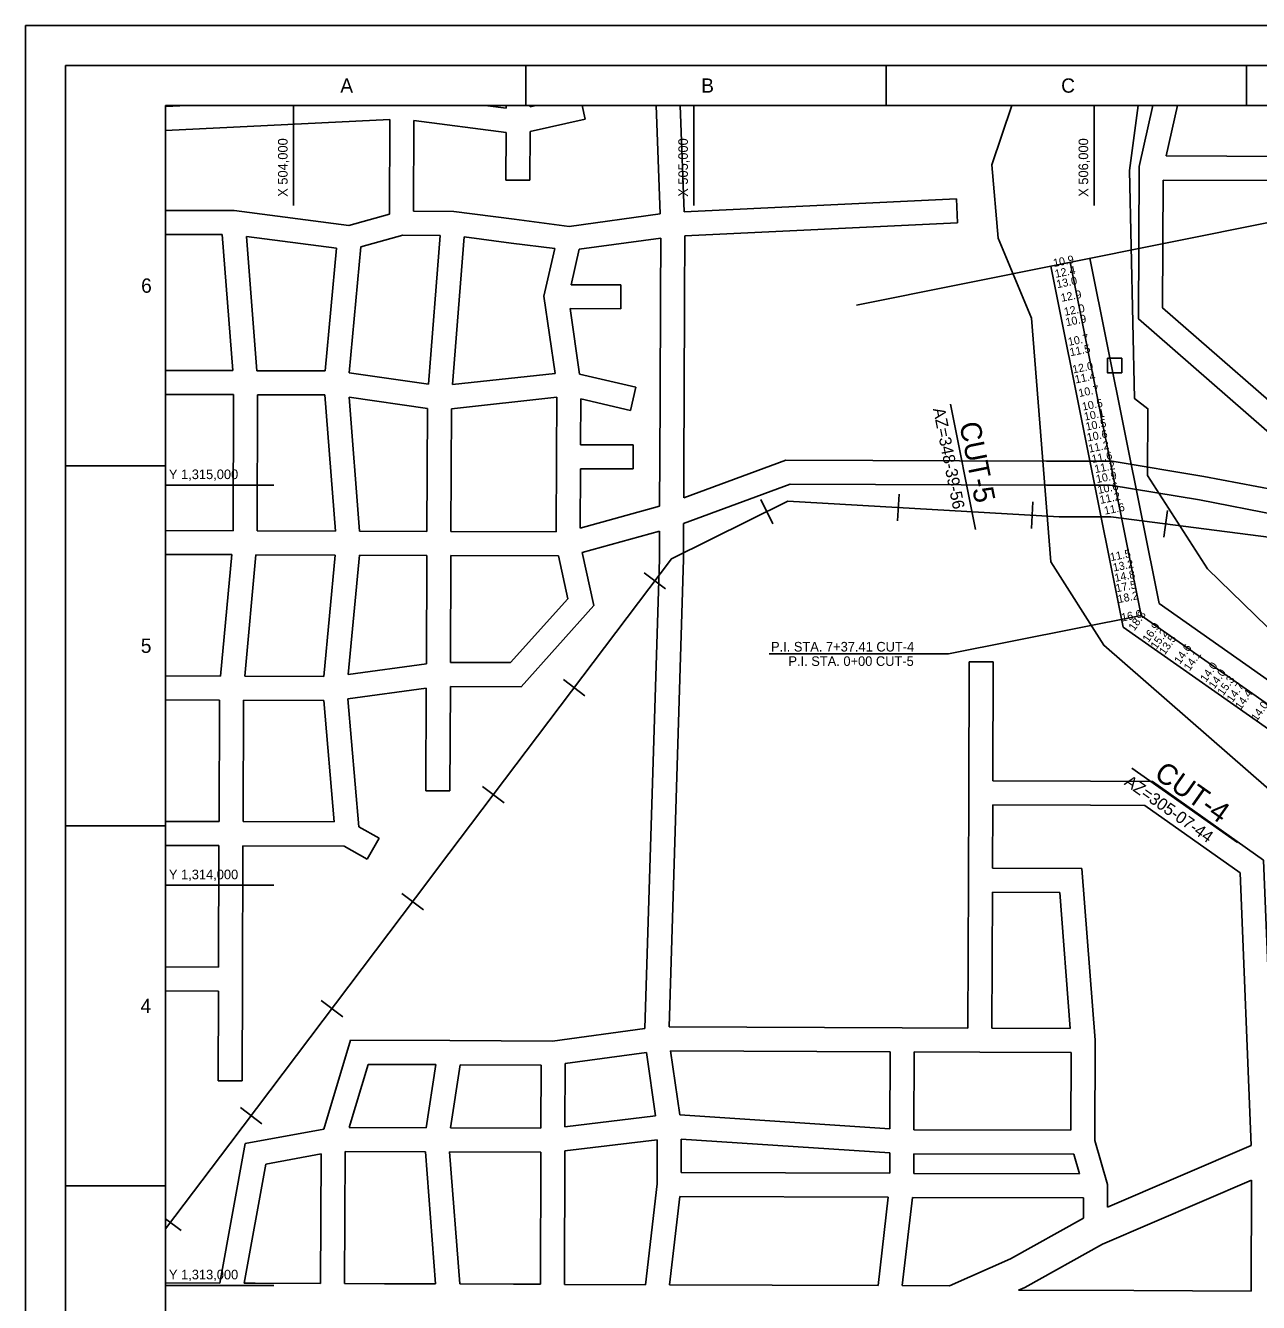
# Model space of a CAD drawing. Extents: x 503330 to 511530, y 1310349 to 1316149.
# Drawn here: x 503330 to 506410, y 1312957 to 1316149 of the extents above; entities that cross this region are included whole.
import ezdxf

# ---------------------------------------------------------------- set-up
doc = ezdxf.new("R2010")
doc.units = 0
for name, color, linetype in [('G-ANNO-TTLB', 7, 'Continuous'), ('Level 2', 7, 'Continuous'), ('Level 23', 7, 'Continuous'), ('Level 3', 7, 'Continuous'), ('Level 32', 7, 'Continuous'), ('Level 37', 7, 'Continuous'), ('Level 49', 7, 'Continuous'), ('Level 5', 7, 'Continuous'), ('Level 50', 7, 'Continuous'), ('Level 51', 7, 'Continuous'), ('Level 52', 7, 'Continuous'), ('Level 56', 7, 'Continuous'), ('Level 58', 7, 'Continuous'), ('Level 6', 7, 'Continuous')]:
    doc.layers.add(name, color=color, linetype=linetype)

msp = doc.modelspace()

# ---------------------------------------------------------------- linework, layer by layer
at = {"layer": 'G-ANNO-TTLB'}
for p, q in [((503430.3, 1316048.5), (503430.3, 1310448.5)), ((511430.3, 1316048.5), (503430.3, 1316048.5)), ((504580.3, 1315948.5), (504580.3, 1316048.5)), ((505480.3, 1315948.5), (505480.3, 1316048.5)), ((506380.3, 1315948.5), (506380.3, 1316048.5)), ((503680.3, 1310548.5), (503680.3, 1315948.5)), ((503680.3, 1315948.5), (511330.3, 1315948.5)), ((503680.3, 1315048.5), (503430.3, 1315048.5)), ((503680.3, 1314148.5), (503430.3, 1314148.5)), ((503680.3, 1313248.5), (503430.3, 1313248.5))]:
    msp.add_line(p, q, dxfattribs=at)
for points in [[(503330.3, 1310348.5), (511530.3, 1310348.5), (511530.3, 1316148.5), (503330.3, 1316148.5)], [(503330.3, 1310348.5), (511530.3, 1310348.5), (511530.3, 1316148.5), (503330.3, 1316148.5)], [(503330.3, 1316148.5), (511530.3, 1316148.5), (511530.3, 1310348.5), (503330.3, 1310348.5)]]:
    msp.add_lwpolyline(points, close=True, dxfattribs=at)
msp.add_lwpolyline([(503330.3, 1316098.5), (503330.3, 1316148.5), (503380.3, 1316148.5)], dxfattribs=at)
at = {"layer": 'Level 2'}
for p, q in [((504000, 1315698.5), (504000, 1315948.5)), ((505000, 1315698.5), (505000, 1315948.5)), ((506000, 1315698.5), (506000, 1315948.5)), ((503680.3, 1315000), (503950.3, 1315000)), ((503680.3, 1314000), (503950.3, 1314000)), ((503680.3, 1313000), (503950.3, 1313000))]:
    msp.add_line(p, q, dxfattribs=at)
at = {"layer": 'Level 23'}
for p, q in [((506392.1, 1313349.5), (506033.2, 1313195.7)), ((506393.2, 1313262.9), (506020.6, 1313103.3)), ((505973.1, 1313168.3), (505790.9, 1313066.7)), ((506020.6, 1313103.3), (505826.8, 1312995.1)), ((505790.9, 1313066.7), (505638.7, 1312998.8)), ((503815.9, 1313005.8), (503680.3, 1313006.3)), ((503903.8, 1313005.4), (503876.8, 1313005.5)), ((504067.5, 1313004.8), (503903.8, 1313005.4)), ((504226.7, 1313004.2), (504127.5, 1313004.6)), ((504354.8, 1313003.7), (504226.7, 1313004.2)), ((504549.5, 1313003), (504415, 1313003.5)), ((504616.4, 1313002.7), (504549.5, 1313003)), ((504878.9, 1313001.7), (504676.4, 1313002.5)), ((505195.3, 1313000.5), (504939.3, 1313001.5)), ((505460.1, 1312999.5), (505195.3, 1313000.5)), ((505638.7, 1312998.8), (505520.5, 1312999.3)), ((505826.8, 1312995.1), (505811.2, 1312988.1))]:
    msp.add_line(p, q, dxfattribs=at)
at = {"layer": 'Level 32'}
for p, q in [((503733.7, 1315948.5), (503680.3, 1315945.9)), ((504530.8, 1315941.8), (504478.9, 1315948.5)), ((504530.8, 1315941.8), (504530.8, 1315948.5)), ((504590.8, 1315945.1), (504590.8, 1315948.5)), ((504606.3, 1315948.5), (504590.8, 1315945.1)), ((504728.7, 1315914.2), (504721.1, 1315948.5)), ((504916.1, 1315677.8), (504905.7, 1315948.5)), ((504975.9, 1315683.2), (504965.7, 1315948.5)), ((506112.2, 1315796), (506146.7, 1315948.5)), ((506179.7, 1315822.5), (506208.2, 1315948.5)), ((504240.1, 1315913.7), (503680.3, 1315885.8)), ((504239.2, 1315677.2), (504240.1, 1315913.7)), ((504299.3, 1315684.2), (504300.1, 1315911.1)), ((504530.6, 1315881.4), (504300.1, 1315911.1)), ((504728.7, 1315914.2), (504590.6, 1315883.6)), ((504530.1, 1315762.4), (504530.6, 1315881.4)), ((504590.1, 1315762.2), (504590.6, 1315883.6)), ((506492, 1315821.3), (506179.7, 1315822.5)), ((504530.1, 1315762.4), (504590.1, 1315762.2)), ((506478.3, 1315761.4), (506172.1, 1315762.5)), ((505656.1, 1315715.4), (504975.9, 1315683.2)), ((505658.9, 1315655.4), (505656.1, 1315715.4)), ((503851.4, 1315686), (503680.3, 1315686.6)), ((504137.7, 1315649), (503851.4, 1315686)), ((504400.3, 1315683.8), (504299.3, 1315684.2)), ((504550.9, 1315664.5), (504400.3, 1315683.8)), ((504239.2, 1315677.2), (504137.7, 1315649)), ((504688.6, 1315646.7), (504550.9, 1315664.5)), ((504916.1, 1315677.8), (504688.6, 1315646.7)), ((505658.9, 1315655.4), (504977, 1315623.1)), ((503821.7, 1315626.1), (503680.3, 1315626.6)), ((503847.8, 1315286.1), (503821.7, 1315626.1)), ((503908, 1315285.8), (503882.2, 1315621.5)), ((504107.3, 1315592.4), (503882.2, 1315621.5)), ((504273.2, 1315624.3), (504167.8, 1315595.1)), ((504365.9, 1315624), (504273.2, 1315624.3)), ((504336.9, 1315252), (504365.9, 1315624)), ((504397, 1315251.5), (504425.7, 1315620.1)), ((504543.2, 1315605), (504425.7, 1315620.1)), ((504917, 1315617.4), (504713.4, 1315589.5)), ((504916.4, 1315470.1), (504917, 1315617.4)), ((504976.4, 1315469.9), (504977, 1315623.1)), ((504078.8, 1315285.2), (504107.3, 1315592.4)), ((504138.7, 1315280.7), (504167.8, 1315595.1)), ((504652.2, 1315590.9), (504543.2, 1315605)), ((504625.4, 1315472.3), (504652.2, 1315590.9)), ((504693.4, 1315500.9), (504713.4, 1315589.5)), ((504817.4, 1315500.5), (504693.4, 1315500.9)), ((504817.2, 1315440.5), (504817.4, 1315500.5)), ((504653.2, 1315279.3), (504625.4, 1315472.3)), ((504915.5, 1315215.6), (504916.4, 1315470.1)), ((504975.4, 1315215.4), (504976.4, 1315469.9)), ((504817.2, 1315440.5), (504690.5, 1315441)), ((504714.1, 1315277.5), (504690.5, 1315441)), ((503847.8, 1315286.1), (503680.3, 1315286.7)), ((504078.8, 1315285.2), (503908, 1315285.8)), ((504336.9, 1315252), (504138.7, 1315280.7)), ((504653.2, 1315279.3), (504397, 1315251.5)), ((504855.3, 1315245.1), (504714.1, 1315277.5)), ((504841.9, 1315186.6), (504855.3, 1315245.1)), ((503850.1, 1315226.1), (503680.3, 1315226.7)), ((503848.8, 1314886.1), (503850.1, 1315226.1)), ((503908.8, 1314885.9), (503910.1, 1315225.8)), ((504078.4, 1315225.2), (503910.1, 1315225.8)), ((504104.5, 1314885.2), (504078.4, 1315225.2)), ((504334.2, 1315191.8), (504139, 1315220)), ((504164.7, 1314884.9), (504139, 1315220)), ((504657.2, 1315219.4), (504394.2, 1315190.8)), ((504656.6, 1315071.2), (504657.2, 1315219.4)), ((504716.7, 1315100.9), (504717.2, 1315215.2)), ((504841.9, 1315186.6), (504717.2, 1315215.2)), ((504914.9, 1315070.2), (504915.5, 1315215.6)), ((504974.9, 1315070), (504975.4, 1315215.4)), ((504333, 1314884.3), (504334.2, 1315191.8)), ((504393, 1314884.1), (504394.2, 1315190.8)), ((504848.2, 1315100.4), (504716.7, 1315100.9)), ((504847.9, 1315040.4), (504848.2, 1315100.4)), ((504655.9, 1314883), (504656.6, 1315071.2)), ((504914.4, 1314947.5), (504914.9, 1315070.2)), ((504974.5, 1314967.8), (504974.9, 1315070)), ((506045, 1315059.5), (505881.1, 1315060.1)), ((506045, 1315059.5), (506273.6, 1315021.9)), ((504715.9, 1314892.4), (504716.5, 1315040.9)), ((504847.9, 1315040.4), (504716.5, 1315040.9)), ((506273.6, 1315021.9), (506450.8, 1314987.9)), ((506039.9, 1314999.5), (505880.9, 1315000.2)), ((506039.9, 1314999.5), (506263, 1314962.8)), ((504914.4, 1314947.5), (504715.9, 1314892.4)), ((506263, 1314962.8), (506459, 1314925.2)), ((503848.8, 1314886.1), (503680.3, 1314886.8)), ((504104.5, 1314885.2), (503908.8, 1314885.9)), ((504333, 1314884.3), (504164.7, 1314884.9)), ((504655.9, 1314883), (504393, 1314884.1)), ((504914.2, 1314885.2), (504721.1, 1314831.6)), ((504913.9, 1314816.1), (504914.2, 1314885.2)), ((504973.9, 1314815.1), (504974.3, 1314903.8)), ((503845.8, 1314826.2), (503680.3, 1314826.8)), ((503817.6, 1314522.7), (503845.8, 1314826.2)), ((503877.9, 1314522.5), (503906, 1314825.9)), ((504104, 1314825.2), (503906, 1314825.9)), ((504075.9, 1314521.7), (504104, 1314825.2)), ((504136.6, 1314526.5), (504164.3, 1314824.9)), ((504332.8, 1314824.3), (504164.3, 1314824.9)), ((504331.8, 1314553.2), (504332.8, 1314824.3)), ((504391.8, 1314556.9), (504392.8, 1314824.1)), ((504661.6, 1314823), (504392.8, 1314824.1)), ((504684.9, 1314716), (504661.6, 1314823)), ((504750.1, 1314698.8), (504721.1, 1314831.6)), ((504877.8, 1313642.3), (504913.9, 1314816.1)), ((504938, 1313645.9), (504973.9, 1314815.1)), ((504542, 1314556.3), (504684.9, 1314716)), ((504568.7, 1314496.2), (504750.1, 1314698.8)), ((504331.8, 1314553.2), (504136.6, 1314526.5)), ((504542, 1314556.3), (504391.8, 1314556.9)), ((505686.5, 1314231.1), (505687.8, 1314558.3)), ((505687.8, 1314558.3), (505747.8, 1314558)), ((505746.7, 1314260.8), (505747.8, 1314558)), ((503817.6, 1314522.7), (503680.3, 1314523.2)), ((504075.9, 1314521.7), (503877.9, 1314522.5)), ((504331.5, 1314492.6), (504135.5, 1314465.8)), ((504330.5, 1314236.2), (504331.5, 1314492.6)), ((504390.5, 1314236), (504391.6, 1314496.9)), ((504568.7, 1314496.2), (504391.6, 1314496.9)), ((503814.8, 1314462.7), (503680.3, 1314463.2)), ((503813.7, 1314159.2), (503814.8, 1314462.7)), ((503873.7, 1314158.9), (503874.8, 1314462.5)), ((504075.7, 1314461.7), (503874.8, 1314462.5)), ((504101.5, 1314158.1), (504075.7, 1314461.7)), ((504162.7, 1314146.2), (504135.5, 1314465.8)), ((505991.1, 1314259.9), (505746.7, 1314260.8)), ((504330.5, 1314236.2), (504390.5, 1314236)), ((505685.7, 1314012.9), (505686.5, 1314231.1)), ((505745.8, 1314042.7), (505746.4, 1314200.8)), ((505990.9, 1314199.9), (505746.4, 1314200.8)), ((503813.7, 1314159.2), (503680.3, 1314159.7)), ((504101.5, 1314158.1), (503873.7, 1314158.9)), ((504213.4, 1314117.4), (504162.7, 1314146.2)), ((504183.7, 1314065.2), (504213.4, 1314117.4)), ((503813.4, 1314099.2), (503680.3, 1314099.7)), ((503812.3, 1313795.6), (503813.4, 1314099.2)), ((503872.2, 1313765.4), (503873.4, 1314098.9)), ((504126.1, 1314098), (503873.4, 1314098.9)), ((504183.7, 1314065.2), (504126.1, 1314098)), ((505969.5, 1314041.9), (505745.8, 1314042.7)), ((506002.5, 1313613), (505969.5, 1314041.9)), ((505684.3, 1313643), (505685.7, 1314012.9)), ((505744.3, 1313642.8), (505745.6, 1313982.7)), ((505913.9, 1313982.1), (505745.6, 1313982.7)), ((505940.1, 1313642.1), (505913.9, 1313982.1)), ((503812.3, 1313795.6), (503680.3, 1313796.1)), ((503871.2, 1313510.9), (503872.2, 1313765.4)), ((503812, 1313735.6), (503680.3, 1313736.1)), ((503811.2, 1313511.1), (503812, 1313735.6)), ((504877.8, 1313642.3), (504646.6, 1313610.6)), ((505520.6, 1313643.7), (504938, 1313645.9)), ((505684.3, 1313643), (505520.6, 1313643.7)), ((505940.1, 1313642.1), (505744.3, 1313642.8)), ((504075.4, 1313390.8), (504142, 1313612.6)), ((504390.4, 1313611.6), (504142, 1313612.6)), ((504646.6, 1313610.6), (504390.4, 1313611.6)), ((506001.5, 1313361.7), (506002.5, 1313613)), ((504881.6, 1313582.2), (504678.5, 1313554.4)), ((504904.4, 1313423.8), (504881.6, 1313582.2)), ((504964.7, 1313426.1), (504941.7, 1313585.9)), ((505490.4, 1313583.8), (504941.7, 1313585.9)), ((505489.6, 1313391.2), (505490.4, 1313583.8)), ((505549.6, 1313389.1), (505550.4, 1313583.5)), ((505714.1, 1313582.9), (505550.4, 1313583.5)), ((505942.4, 1313582.1), (505714.1, 1313582.9)), ((505941.6, 1313387.6), (505942.4, 1313582.1)), ((504139.2, 1313394.5), (504186.6, 1313552.4)), ((504355.4, 1313551.8), (504186.6, 1313552.4)), ((504331.4, 1313393.7), (504355.4, 1313551.8)), ((504392.1, 1313393.5), (504416.1, 1313551.5)), ((504618.5, 1313550.7), (504416.1, 1313551.5)), ((504617.9, 1313392.6), (504618.5, 1313550.7)), ((504677.9, 1313396.4), (504678.5, 1313554.4)), ((503811.2, 1313511.1), (503871.2, 1313510.9)), ((504904.4, 1313423.8), (504677.9, 1313396.4)), ((505489.6, 1313391.2), (504964.7, 1313426.1)), ((504075.4, 1313390.8), (503879.2, 1313354.8)), ((504331.4, 1313393.7), (504139.2, 1313394.5)), ((504617.9, 1313392.6), (504392.1, 1313393.5)), ((505941.6, 1313387.6), (505549.6, 1313389.1)), ((503815.9, 1313005.8), (503879.2, 1313354.8)), ((504908.4, 1313363.9), (504677.7, 1313335.9)), ((504907.9, 1313254.1), (504908.4, 1313363.9)), ((504968, 1313282.2), (504968.4, 1313365.7)), ((505489.4, 1313331.1), (504968.4, 1313365.7)), ((506033.4, 1313252.5), (506001.5, 1313361.7)), ((504068.8, 1313328.6), (503930.9, 1313303.2)), ((504067.5, 1313004.8), (504068.8, 1313328.6)), ((504127.5, 1313004.6), (504128.8, 1313334.5)), ((504329.4, 1313333.7), (504128.8, 1313334.5)), ((504354.8, 1313003.7), (504329.4, 1313333.7)), ((504617.7, 1313332.6), (504389.6, 1313333.5)), ((504415, 1313003.5), (504389.6, 1313333.5)), ((504616.4, 1313002.7), (504617.7, 1313332.6)), ((504676.4, 1313002.5), (504677.7, 1313335.9)), ((505489.2, 1313280.2), (505489.4, 1313331.1)), ((505549.2, 1313280), (505549.4, 1313329.1)), ((505949, 1313327.5), (505549.4, 1313329.1)), ((505963.3, 1313278.4), (505949, 1313327.5)), ((503876.8, 1313005.5), (503930.9, 1313303.2)), ((505489.2, 1313280.2), (504968, 1313282.2)), ((505963.3, 1313278.4), (505549.2, 1313280)), ((506393.2, 1313262.9), (506392.1, 1312985.9)), ((504878.9, 1313001.7), (504907.9, 1313254.1)), ((506033.2, 1313195.7), (506033.4, 1313252.5)), ((504939.3, 1313001.5), (504964.7, 1313222.2)), ((505485.5, 1313220.2), (504964.7, 1313222.2)), ((505460.1, 1312999.5), (505485.5, 1313220.2)), ((505520.5, 1312999.3), (505545.8, 1313220)), ((505973.3, 1313218.4), (505545.8, 1313220)), ((505973.1, 1313168.3), (505973.3, 1313218.4)), ((506099.2, 1312987.1), (505811.2, 1312988.1)), ((506392.1, 1312985.9), (506099.2, 1312987.1))]:
    msp.add_line(p, q, dxfattribs=at)
for points in [[(506516.5, 1315061.3), (506110.8, 1315415.5), (506112.2, 1315796)], [(506552.6, 1315109.4), (506170.9, 1315442.7), (506172.1, 1315762.5)], [(505881.1, 1315060.2), (505230, 1315062.6), (504974.5, 1314967.8)], [(505880.9, 1315000.2), (505240.6, 1315002.6), (504974.3, 1314903.8)], [(506451.4, 1313369.7), (506423.2, 1314062.5), (506145.9, 1314259.3), (505991.1, 1314259.9)], [(506392.1, 1313349.5), (506364.5, 1314030.7), (506126.6, 1314199.4), (505990.9, 1314199.9)]]:
    msp.add_lwpolyline(points, dxfattribs=at)
at = {"layer": 'Level 37'}
for p, q in [((505508.8, 1314910.4), (505512.6, 1314977.7)), ((505197.4, 1314903.6), (505167.5, 1314964)), ((505843.1, 1314891.2), (505846.9, 1314958.5)), ((506174.3, 1314869.5), (506182.9, 1314936.2)), ((504929.4, 1314740.5), (504875.7, 1314781.1)), ((504727.7, 1314473.2), (504674, 1314513.8)), ((504526, 1314206), (504472.2, 1314246.5)), ((504324.3, 1313938.6), (504270.6, 1313979.2)), ((504122.6, 1313671.4), (504068.8, 1313711.9)), ((503920.9, 1313404.1), (503867.1, 1313444.7)), ((503719.1, 1313136.9), (503680.3, 1313166.1))]:
    msp.add_line(p, q, dxfattribs=at)
msp.add_lwpolyline([(503680.3, 1313141.4), (503840.6, 1313353.6), (504337.7, 1314012.3), (504359.8, 1314041.6), (504943.9, 1314815.6), (505235, 1314959.9), (505912.9, 1314921), (506042, 1314920.5), (506332.5, 1314883), (506622.9, 1314845.6), (507107.2, 1314843.7), (507365.8, 1314951.8), (507624.4, 1315023.6), (507915.4, 1315131.5), (508206.5, 1315275.9), (508465.2, 1315384), (508723.7, 1315455.7), (509047, 1315563.6)], dxfattribs=at)
at = {"layer": 'Level 5'}
for points in [[(505794, 1315948.5), (505744.2, 1315800.6), (505760.3, 1315617.2), (505843.1, 1315416.9), (505891.3, 1314808.3), (506024, 1314599.6), (506647.4, 1314056), (507642.5, 1313099.9), (507702.7, 1313024.1), (507718.9, 1312844.3), (507743.6, 1312727.6), (507768.6, 1312719.2), (507933.4, 1312101.9), (507890.2, 1311593.7)], [(508324.1, 1311750.7), (508174.9, 1312042.9), (508101.5, 1312576.5), (508071.4, 1312743.4), (508047.3, 1312868.5), (508036.4, 1312983.7), (507933.5, 1313150.3), (507770.5, 1313344.2), (506282.9, 1314790.5), (506133.6, 1315024.3), (506134.1, 1315191), (506100.8, 1315216.1), (506088.6, 1315786), (506110.2, 1315948.5)]]:
    msp.add_lwpolyline(points, dxfattribs=at)
at = {"layer": 'Level 50'}
for p, q in [((506162.3, 1314703.9), (505989.4, 1315566.8)), ((506072.1, 1314645.1), (505891.3, 1315547.1)), ((506753.5, 1314288), (506162.3, 1314703.9)), ((506687.2, 1314212.4), (506072.1, 1314645.1))]:
    msp.add_line(p, q, dxfattribs=at)
at = {"layer": 'Level 51'}
for p, q in [((505703.4, 1314889.3), (505640.7, 1315202.4)), ((506358.3, 1314107.1), (506094.2, 1314292.9))]:
    msp.add_line(p, q, dxfattribs=at)
at = {"layer": 'Level 52'}
msp.add_lwpolyline([(506033, 1315316.9), (506069, 1315316.9), (506069, 1315280.9), (506033, 1315280.9)], close=True, dxfattribs=at)
at = {"layer": 'Level 56'}
for q in [(506117.2, 1314674.5), (505188.3, 1314578.1)]:
    msp.add_line((505636.2, 1314578.1), q, dxfattribs=at)
at = {"layer": 'Level 58'}
msp.add_line((505406.1, 1315449.9), (506448.3, 1315658.8), dxfattribs=at)
at = {"layer": 'Level 6'}
for p, q in [((506117.2, 1314674.5), (505940.3, 1315556.9)), ((506720.3, 1314250.2), (506117.2, 1314674.5))]:
    msp.add_line(p, q, dxfattribs=at)

# ---------------------------------------------------------------- texts
at = {"layer": 'G-ANNO-TTLB'}
for s, p in [('A', (504116.7, 1315980.7)), ('B', (505018.3, 1315980.7)), ('C', (505917.5, 1315980.7)), ('6', (503619.1, 1315480.7)), ('5', (503618.3, 1314580.7)), ('4', (503617.5, 1313680.7))]:
    msp.add_text(s, height=35.7, dxfattribs=at).set_placement(p)
at = {"layer": 'Level 3'}
for s, p in [('X 504,000', (503985, 1315720.5)), ('X 505,000', (504985, 1315720.5)), ('X 506,000', (505985, 1315720.5))]:
    msp.add_text(s, height=24, rotation=90, dxfattribs=at).set_placement(p)
for s, p in [('Y 1,315,000', (503688.5, 1315015)), ('Y 1,314,000', (503688.5, 1314015)), ('Y 1,313,000', (503688.5, 1313015))]:
    msp.add_text(s, height=24, dxfattribs=at).set_placement(p)
at = {"layer": 'Level 49'}
for s, rotation, p in [('10.9 ', 11.3343, (505899.7, 1315545)), ('12.4 ', 11.3343, (505903.7, 1315518)), ('13.0 ', 11.3343, (505907.7, 1315492)), ('12.9 ', 11.3343, (505918.7, 1315458)), ('12.0 ', 11.3343, (505926.7, 1315423)), ('10.9 ', 11.3343, (505930.7, 1315397)), ('10.7 ', 11.3343, (505936.7, 1315348)), ('11.5 ', 11.3343, (505940.7, 1315322)), ('12.0 ', 11.3343, (505947.7, 1315279)), ('11.4 ', 11.3343, (505953.7, 1315254)), ('10.7 ', 11.3343, (505962.7, 1315220)), ('10.5 ', 11.3343, (505971.7, 1315186)), ('10.1 ', 11.3343, (505976.7, 1315161)), ('10.5 ', 11.3343, (505980.7, 1315136)), ('10.6 ', 11.3343, (505983.7, 1315109)), ('11.2 ', 11.3343, (505987.7, 1315081)), ('11.6 ', 11.3343, (505995.7, 1315055)), ('11.2 ', 11.3343, (506002.7, 1315030)), ('10.9 ', 11.3343, (506006.7, 1315005)), ('10.6 ', 11.3343, (506010.7, 1314978)), ('11.2 ', 11.3343, (506015.7, 1314953)), ('11.6 ', 11.3343, (506026.7, 1314926)), ('11.5 ', 11.3343, (506041.7, 1314810)), ('13.2 ', 11.3343, (506048.7, 1314784)), ('14.8 ', 11.3343, (506052.7, 1314758)), ('17.5 ', 11.3343, (506055.7, 1314732)), ('18.2 ', 11.3343, (506060.7, 1314705)), ('16.0 ', 11.3343, (506069.7, 1314659)), ('18.3 ', 54.8711, (506100.4, 1314634.2)), ('16.9 ', 54.8711, (506135.4, 1314605.2)), ('15.2 ', 54.8711, (506155.4, 1314588.2)), ('13.5 ', 54.8711, (506176.4, 1314574.2)), ('14.6 ', 54.8711, (506214.4, 1314551.2)), ('14.1 ', 54.8711, (506238.4, 1314534.2)), ('14.0 ', 54.8711, (506279.4, 1314506.2)), ('14.0 ', 54.8711, (506300.4, 1314489.2)), ('15.3 ', 54.8711, (506322.4, 1314472.2)), ('14.7 ', 54.8711, (506345.4, 1314455.2)), ('14.4 ', 54.8711, (506366.4, 1314437.2)), ('14.0 ', 54.8711, (506406.4, 1314408.2))]:
    msp.add_text(s, height=20, rotation=rotation, dxfattribs=at).set_placement(p)
at = {"layer": 'Level 51'}
for s, height, rotation, p in [('AZ=348-39-56', 30, 281.3343, (505597.2, 1315190.3)), ('CUT-5', 52, 281.3343, (505662.8, 1315153.1)), ('CUT-4', 52, 324.8711, (506146.8, 1314270.5)), ('AZ=305-07-44', 30, 324.8711, (506073.1, 1314252.7))]:
    msp.add_text(s, height=height, rotation=rotation, dxfattribs=at).set_placement(p)
at = {"layer": 'Level 56'}
for s, p in [('P.I. STA. 7+37.41 CUT-4', (505192.7, 1314584.1)), ('P.I. STA. 0+00 CUT-5', (505236.2, 1314548.1))]:
    msp.add_text(s, height=24, dxfattribs=at).set_placement(p)

doc.saveas('drawing.dxf')
